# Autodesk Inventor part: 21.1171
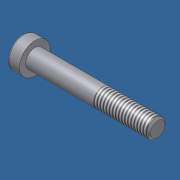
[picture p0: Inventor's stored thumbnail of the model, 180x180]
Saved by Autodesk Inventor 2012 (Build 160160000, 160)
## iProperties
Created: 2006-02
Part Number: 21.1171
Material: Steel, Mild
Description: M6 X 50 SHCS
Document SubType Name: Modeling
Standard: DIN 7984
Designer: Andy Moles
Standards Organization: DIN
Language: en-US
Size Designation: M6 x 40
Categories: <MemberInstance><Categories><Category DisplayName="Fasteners" InternalName="e4da775c-781d-43d5-af7c-5136215cf5a6" Mnemonic="FSTN"><Category DisplayName="Bolts"
Density: 7.86 g/cm^3
Mass: 13.1529 g
Surface Area: 12.5505 cm^2
Volume: 1.6734 cm^3
Author: Andy Moles
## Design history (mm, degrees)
body "Solid1"
workplane "Work Plane1"
revolve "Body" stored, may be unused: angle "d10" = 90 deg
sketch "Sketch2"
  geometry: L1 (0, -6)-(0, 8) reference; L2 (-6, 0)-(8, 0) reference; L3 (2.309, 0)-(1.155, -2); L4 (1.155, -2)-(-1.155, -2); L5 (-1.155, -2)-(-2.309, 0); L6 (-2.309, 0)-(-1.155, 2); L7 (-1.155, 2)-(1.155, 2); L8 (1.155, 2)-(2.309, 0); 2 further points
  constraints: 12 end point, 1 coincident, 1 horizontal alignment, 1 point on line, 12 other
extrude "Slot" join sketch "Sketch2" stored distance "d11" = 10; taper "d12" = 0 deg
fillet "Fillet1" dims "d17" = 0.6 (= RR)
feature "Thread" dims "d13" = 18 (= GEL), "d14" = 0
chamfer "Chamfer1" distance "d15" = 0.61345 (= -0.5 x SPD + 0.5 x GD); stored, may be unused: second distance "d16" = 0.61345 (= GUL), angle "d27" = 45 deg
sketch "Sketch1"
  geometry: L1 (0.333, 0)-(50, 0); L2 (50, 0)-(50, 3); L3 (50, 3)-(32, 3); L4 (32, 3)-(31.386, 3); L5 (31.386, 3)-(0, 3); L6 (0, 3)-(0, 5); L7 (0, 5)-(-4, 5); L8 (-4, 5)-(-4, 2.309); L9 (-4, 2.309)-(-1, 2.309); L10 (-1, 2.309)-(0.333, 0); L11 (-8.4, 0)-(53.2, 0) reference; L12 (0, -0.5)-(0, 6.5) reference; L13 (32, 3)-(0, 3)
  constraints: 22 end point, 6 parallel, 2 collinear, 2 perpendicular, 1 horizontal, 1 midpoint
  dimensions: "d1" = 18 distance from line of L3.end L2 (= GEL); "d2" = 0.61355 distance of L4.end L3.end (computed from GAL); "d3" = 4 distance between parallel lines of L8 L6 (= KOH); "d4" = 3 distance of L8.end L9.end (= INTI); "d5" = 60 deg angle of L10 L1; "d6" = 6 diameter of L3 L1 (= GD); "d7" = 6 diameter of L5 L1 (= BDM); "d8" = 4.6188 diameter of L9 L1 (= 1.1547 x SW); "d9" = 10 diameter of L7 L1 (= KOD); "d26" = 50 distance between parallel lines of L12 L2 (= NLG)
other parameters: "GD" = 6 (= NND) [user parameter; used in 2 equation terms], "NLG" = 50 [user parameter; used in 1 equation term], "GEL" = 18 [user parameter; used in 2 equation terms], "KOD" = 10 [user parameter; used in 1 equation term], "KOH" = 4 [user parameter; used in 1 equation term], "INTI" = 3 [user parameter; used in 1 equation term], "GAL" = 0.61345 (= 0.61345 x PTC) [user parameter; used in 1 equation term], "GUL" = 0.61345 (= 0.61345 x PTC) [user parameter; used in 1 equation term], "BDM" = 6 (= NND) [user parameter; used in 1 equation term], "SW" = 4 [user parameter; used in 2 equation terms], "RR" = 0.6 [user parameter; used in 1 equation term], "SPD" = 4.7731 (= NND - 1.2269 x PTC) [user parameter; used in 1 equation term], "d19" = 0, "d28" = 0, "d29" = 0, "TOA" = 30 deg [user parameter], "GD1" = 4.7731 (= THREADDIA - 1.2269 x PTC) [user parameter], "THREADDIA" = 6 [user parameter; used in 1 equation term], "FAWI" = 45 deg [user parameter], "ANG" = 120 deg [user parameter], "PTC" = 1 [user parameter; used in 5 equation terms], "NND" = 6 [user parameter; used in 3 equation terms], "E0" = 4.62 (= 1.155 x SW) [user parameter]
